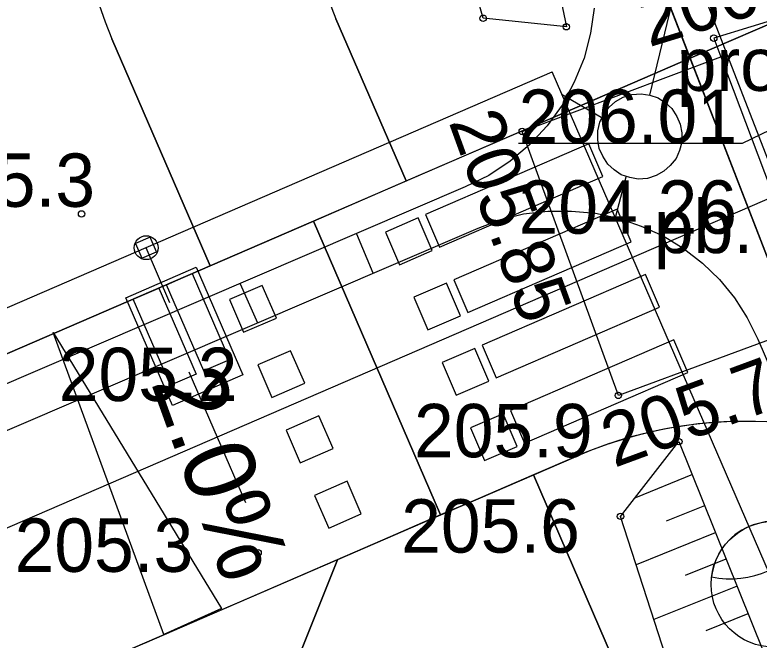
# Model space of a CAD drawing. Extents: x 6512606 to 6513006, y 6022524 to 6022728.
# Drawn here: x 6512842.35 to 6512852.81, y 6022585.95 to 6022594.74 of the extents above; entities that cross this region are included whole.
import ezdxf

# ---------------------------------------------------------------- set-up
doc = ezdxf.new("R2010")
doc.units = 0
for name, color, linetype in [('000 Inne (niezydentyfikowane)', 7, 'Continuous'), ('217-kontur klasyfikacyjny', 7, 'Continuous'), ('218-kontur użytku gruntowego', 7, 'Continuous'), ('219-działka ewidencyjna', 7, 'Continuous'), ('4', 7, 'Continuous'), ('Default', 7, 'Continuous'), ('E_OSW_KABLE', 7, 'Continuous'), ('E_OSW_LAMPA', 7, 'Continuous'), ('jezdnia', 7, 'Continuous'), ('kolor_chodnik', 7, 'Continuous'), ('kolor_kostka_bet', 7, 'Continuous'), ('kolor_sc_rowerowa', 7, 'Continuous'), ('krawężnik', 7, 'Continuous'), ('Level 60', 7, 'Continuous'), ('maxp_kan_deszczowa', 7, 'Continuous'), ('maxp_kraw_nawierzchni', 7, 'Continuous'), ('maxp_krawężnik', 7, 'Continuous'), ('maxp_obrzeże', 7, 'Continuous'), ('maxp_opornik', 7, 'Continuous'), ('maxp_os', 7, 'Continuous'), ('maxp_poziome', 7, 'Continuous'), ('maxp_przechyłki', 7, 'Continuous'), ('maxp_ramka_2', 7, 'Continuous'), ('obszar utwardzony', 7, 'Continuous'), ('obszar utwardzony-Atr17', 7, 'Continuous'), ('pikieta naturalna', 7, 'Continuous'), ('pikieta naturalna-Atr2', 7, 'Continuous'), ('pikieta sztuczna', 7, 'Continuous'), ('pikieta sztuczna-Atr2', 7, 'Continuous'), ('przewód kanalizacyjny - projektowany lub w budowie (linia) - ob. projektowany', 7, 'Continuous'), ('punkt o określonej wysokości (sieć kanalizacyjna)-Atr2', 7, 'Continuous'), ('punkt o określonej wysokości (sieć kanalizacyjna)-Atr3', 7, 'Continuous'), ('punkt wysokościowy naturalny-Atr2', 7, 'Continuous'), ('skarpa nieumocniona', 7, 'Continuous'), ('urządzenie techniczne projektowane lub w budowie (sieć kanalizacyjna) - powierzchnia - ob. projektowany', 7, 'Continuous'), ('urządzenie techniczne projektowane lub w budowie (sieć kanalizacyjna) - powierzchnia - ob. projektowany-Atr17', 7, 'Continuous')]:
    doc.layers.add(name, color=color, linetype=linetype)

# ---------------------------------------------------------------- blocks, each defined once
blk = doc.blocks.new('PW01')
at = {"layer": 'Default'}
blk.add_circle((0, 0), 0.45, dxfattribs=at)
blk = doc.blocks.new('RLX_5XB31K2B408A_46W_1')
at = {"layer": 'Default'}
for p, q in [((-53.8, 53.6), (-53.8, 218.5)), ((-53.8, 218.5), (54.2, 218.5)), ((54.2, 218.5), (54.2, 53.6)), ((-44.8, 59.5), (-44.8, 191.5)), ((-44.8, 191.5), (-5.8, 191.5)), ((-5.8, 191.5), (-5.8, 59.5)), ((6.2, 59.5), (6.2, 191.5)), ((6.2, 191.5), (45.2, 191.5)), ((45.2, 191.5), (45.2, 59.5)), ((-0.1, 84.6), (-0.1, 0.4)), ((54.2, 53.6), (-53.8, 53.6)), ((-5.8, 59.5), (-44.8, 59.5)), ((45.2, 59.5), (6.2, 59.5))]:
    blk.add_line(p, q, dxfattribs=at)
blk.add_lwpolyline([(11.2, -10.8), (11.2, 11.6), (-11.3, 11.6), (-11.3, -10.8)], close=True, dxfattribs=at)
blk.add_circle((-0.1, 0.4), 16.8, dxfattribs=at)

msp = doc.modelspace()

# ---------------------------------------------------------------- linework, layer by layer
at = {"layer": '000 Inne (niezydentyfikowane)'}
for points in [[(6512850.09, 6022594.6), (6512850.05, 6022594.59)], [(6512851.87, 6022588.28), (6512851.07, 6022587.95)], [(6512852.04, 6022587.84), (6512851.5, 6022587.62)], [(6512852.19, 6022587.46), (6512851.08, 6022587.01)], [(6512852.34, 6022587.09), (6512851.77, 6022586.86)], [(6512852.5, 6022586.71), (6512851.33, 6022586.24)], [(6512852.65, 6022586.32), (6512852.06, 6022586.08)]]:
    msp.add_lwpolyline(points, dxfattribs=at)
at = {"layer": '217-kontur klasyfikacyjny'}
msp.add_lwpolyline([(6512855.78, 6022583.95), (6512848.55, 6022602.62)], dxfattribs=at)
at = {"layer": '218-kontur użytku gruntowego'}
for points in [[(6512848.55, 6022602.62), (6512855.78, 6022583.95)], [(6512855.78, 6022583.95), (6512848.55, 6022602.62)]]:
    msp.add_lwpolyline(points, dxfattribs=at)
at = {"layer": '219-działka ewidencyjna'}
msp.add_lwpolyline([(6512855.78, 6022583.95), (6512848.55, 6022602.62)], dxfattribs=at)
at = {"layer": '4'}
msp.add_lwpolyline([(6512855.78, 6022583.95), (6512848.55, 6022602.62)], dxfattribs=at)
at = {"layer": 'E_OSW_KABLE'}
msp.add_line((6512835.613, 6022587.752), (6512849.902, 6022593.935), dxfattribs=at)
msp.add_lwpolyline([(6512855.264, 6022584.708), (6512853.876, 6022584.751), (6512849.902, 6022593.935)], dxfattribs=at)
at = {"layer": 'E_OSW_LAMPA'}
msp.add_circle((6512853.018, 6022586.735), 0.885, dxfattribs=at)
for centre, radius, start, end in [((6512853.018, 6022586.735), 0.885, 53.2802, 173.2802), ((6512852.398, 6022588.175), 1.362, 259.0508, 327.5095)]:
    msp.add_arc(centre, radius, start, end, dxfattribs=at)
at = {"layer": 'jezdnia'}
msp.add_lwpolyline([(6512857.23, 6022588.82), (6512855.05, 6022597.75), (6512854.94, 6022596.77), (6512854.71, 6022596.06), (6512854.24, 6022595.41), (6512853.71, 6022594.99), (6512853.21, 6022594.73), (6512852.17, 6022594.41), (6512852.27, 6022594.15), (6512853.67, 6022590.44), (6512853.87, 6022590.02), (6512854.31, 6022590.11), (6512855.01, 6022590.11), (6512855.7, 6022590.01), (6512856.23, 6022589.8), (6512856.78, 6022589.31)], close=True, dxfattribs=at)
at = {"layer": 'kolor_chodnik'}
for p, q in [((6512851.838, 6022594.128), (6512853.234, 6022594.732)), ((6512846.864, 6022594.682), (6512847.85, 6022592.403)), ((6512850.218, 6022593.427), (6512851.838, 6022594.128)), ((6512847.85, 6022592.403), (6512850.218, 6022593.427)), ((6512850.236, 6022588.532), (6512849.637, 6022588.273)), ((6512849.637, 6022588.273), (6512851.225, 6022584.602))]:
    msp.add_line(p, q, dxfattribs=at)
for centre, radius, start, end in [((6512849.617, 6022595.874), 3, 113.9, 203.397), ((6512852.619, 6022583.025), 6, 48.3268, 113.397)]:
    msp.add_arc(centre, radius, start, end, dxfattribs=at)
at = {"layer": 'kolor_kostka_bet'}
for p, q in [((6512853.234, 6022594.732), (6512851.838, 6022594.128)), ((6512845.097, 6022591.211), (6512843.717, 6022594.401)), ((6512851.838, 6022594.128), (6512850.218, 6022593.427)), ((6512850.218, 6022593.427), (6512846.547, 6022591.839)), ((6512846.547, 6022591.839), (6512835.634, 6022587.117)), ((6512846.547, 6022591.839), (6512848.334, 6022587.709)), ((6512848.334, 6022587.709), (6512846.547, 6022591.839)), ((6512846.547, 6022591.839), (6512848.334, 6022587.709)), ((6512835.634, 6022587.117), (6512845.097, 6022591.211)), ((6512848.859, 6022587.936), (6512850.236, 6022588.532)), ((6512848.334, 6022587.709), (6512848.859, 6022587.936)), ((6512844.176, 6022585.91), (6512848.334, 6022587.709)), ((6512846.363, 6022585.766), (6512846.884, 6022587.081))]:
    msp.add_line(p, q, dxfattribs=at)
msp.add_lwpolyline([(6512846.884, 6022587.081), (6512844.176, 6022585.91), (6512843.862, 6022585.774)], dxfattribs=at)
for centre, radius, start, end in [((6512848.305, 6022596.386), 5, 113.9, 203.397), ((6512852.619, 6022583.025), 6, 14.633, 113.397)]:
    msp.add_arc(centre, radius, start, end, dxfattribs=at)
at = {"layer": 'kolor_sc_rowerowa'}
for p, q in [((6512847.85, 6022592.403), (6512846.864, 6022594.682)), ((6512843.717, 6022594.401), (6512845.097, 6022591.211)), ((6512846.547, 6022591.839), (6512847.85, 6022592.403)), ((6512845.097, 6022591.211), (6512846.547, 6022591.839)), ((6512849.637, 6022588.273), (6512848.859, 6022587.936)), ((6512851.225, 6022584.602), (6512849.637, 6022588.273)), ((6512848.859, 6022587.936), (6512848.334, 6022587.709)), ((6512848.334, 6022587.709), (6512846.884, 6022587.081)), ((6512846.884, 6022587.081), (6512846.363, 6022585.766))]:
    msp.add_line(p, q, dxfattribs=at)
for centre, radius in [((6512848.305, 6022596.386), 5), ((6512849.617, 6022595.874), 3)]:
    msp.add_arc(centre, radius, 113.9, 203.397, dxfattribs=at)
at = {"layer": 'krawężnik'}
msp.add_lwpolyline([(6512857.23, 6022588.82), (6512855.05, 6022597.75), (6512854.94, 6022596.77), (6512854.71, 6022596.06), (6512854.24, 6022595.41), (6512853.71, 6022594.99), (6512853.21, 6022594.73), (6512852.17, 6022594.41), (6512852.27, 6022594.15), (6512853.67, 6022590.44), (6512853.87, 6022590.02), (6512854.31, 6022590.11), (6512855.01, 6022590.11), (6512855.7, 6022590.01), (6512856.23, 6022589.8), (6512856.78, 6022589.31)], close=True, dxfattribs=at)
at = {"layer": 'Level 60'}
msp.add_lwpolyline([(6512844.799, 6022589.721), (6512845.593, 6022587.885)], dxfattribs=at)
at = {"layer": 'maxp_kan_deszczowa'}
msp.add_lwpolyline([(6512855.131, 6022585.797), (6512853.495, 6022589.851), (6512851.482, 6022595.049), (6512848.64, 6022602.387)], dxfattribs=at)
at = {"layer": 'maxp_kraw_nawierzchni'}
for p, q in [((6512847.85, 6022592.403), (6512846.864, 6022594.682)), ((6512848.017, 6022591.885), (6512847.558, 6022591.686)), ((6512848.215, 6022591.426), (6512848.017, 6022591.885)), ((6512847.558, 6022591.686), (6512847.757, 6022591.227)), ((6512847.757, 6022591.227), (6512848.215, 6022591.426)), ((6512845.827, 6022590.936), (6512845.369, 6022590.737)), ((6512846.026, 6022590.477), (6512845.827, 6022590.936)), ((6512848.414, 6022590.967), (6512847.955, 6022590.768)), ((6512848.613, 6022590.508), (6512848.414, 6022590.967)), ((6512845.369, 6022590.737), (6512845.567, 6022590.278)), ((6512847.955, 6022590.768), (6512848.154, 6022590.309)), ((6512845.567, 6022590.278), (6512846.026, 6022590.477)), ((6512848.154, 6022590.309), (6512848.613, 6022590.508)), ((6512851.608, 6022590.172), (6512849.314, 6022589.177)), ((6512851.807, 6022589.713), (6512851.608, 6022590.172)), ((6512846.225, 6022590.018), (6512845.766, 6022589.819)), ((6512846.424, 6022589.56), (6512846.225, 6022590.018)), ((6512848.812, 6022590.049), (6512848.353, 6022589.851)), ((6512849.011, 6022589.591), (6512848.812, 6022590.049)), ((6512845.766, 6022589.819), (6512845.965, 6022589.361)), ((6512848.353, 6022589.851), (6512848.552, 6022589.392)), ((6512849.513, 6022588.719), (6512851.807, 6022589.713)), ((6512848.552, 6022589.392), (6512849.011, 6022589.591)), ((6512845.965, 6022589.361), (6512846.424, 6022589.56)), ((6512849.314, 6022589.177), (6512849.513, 6022588.719)), ((6512846.623, 6022589.101), (6512846.164, 6022588.902)), ((6512846.822, 6022588.642), (6512846.623, 6022589.101)), ((6512846.164, 6022588.902), (6512846.363, 6022588.443)), ((6512846.363, 6022588.443), (6512846.822, 6022588.642)), ((6512851.225, 6022584.602), (6512849.637, 6022588.273)), ((6512847.021, 6022588.183), (6512846.562, 6022587.984)), ((6512847.219, 6022587.724), (6512847.021, 6022588.183)), ((6512846.562, 6022587.984), (6512846.761, 6022587.526)), ((6512846.761, 6022587.526), (6512847.219, 6022587.724))]:
    msp.add_line(p, q, dxfattribs=at)
msp.add_arc((6512849.617, 6022595.874), 3, 113.9, 203.397, dxfattribs=at)
at = {"layer": 'maxp_krawężnik'}
for p, q in [((6512853.234, 6022594.732), (6512850.218, 6022593.427)), ((6512845.097, 6022591.211), (6512835.634, 6022587.117)), ((6512846.884, 6022587.081), (6512841.909, 6022584.929))]:
    msp.add_line(p, q, dxfattribs=at)
msp.add_arc((6512852.619, 6022583.025), 6, 14.633, 94.6616, dxfattribs=at)
at = {"layer": 'maxp_obrzeże'}
for p, q in [((6512845.097, 6022591.211), (6512843.717, 6022594.401)), ((6512846.363, 6022585.766), (6512846.884, 6022587.081))]:
    msp.add_line(p, q, dxfattribs=at)
msp.add_arc((6512848.305, 6022596.386), 5, 113.9, 203.397, dxfattribs=at)
at = {"layer": 'maxp_opornik'}
for p, q in [((6512850.218, 6022593.427), (6512845.097, 6022591.211)), ((6512850.236, 6022588.532), (6512848.859, 6022587.936)), ((6512848.859, 6022587.936), (6512846.884, 6022587.081))]:
    msp.add_line(p, q, dxfattribs=at)
msp.add_arc((6512852.619, 6022583.025), 6, 94.6616, 113.397, dxfattribs=at)
at = {"layer": 'maxp_os'}
msp.add_line((6512859.416, 6022594.955), (6512836.66, 6022585.109), dxfattribs=at)
at = {"layer": 'maxp_poziome'}
for p, q in [((6512850.415, 6022592.924), (6512848.121, 6022591.93)), ((6512850.614, 6022592.465), (6512850.415, 6022592.924)), ((6512848.32, 6022591.471), (6512850.614, 6022592.465)), ((6512850.813, 6022592.007), (6512848.519, 6022591.012)), ((6512851.012, 6022591.548), (6512850.813, 6022592.007)), ((6512848.017, 6022591.885), (6512847.558, 6022591.686)), ((6512848.215, 6022591.426), (6512848.017, 6022591.885)), ((6512848.121, 6022591.93), (6512848.32, 6022591.471)), ((6512847.558, 6022591.686), (6512847.757, 6022591.227)), ((6512848.718, 6022590.554), (6512851.012, 6022591.548)), ((6512847.757, 6022591.227), (6512848.215, 6022591.426)), ((6512851.21, 6022591.089), (6512848.917, 6022590.095)), ((6512851.409, 6022590.63), (6512851.21, 6022591.089)), ((6512845.827, 6022590.936), (6512845.369, 6022590.737)), ((6512846.026, 6022590.477), (6512845.827, 6022590.936)), ((6512848.414, 6022590.967), (6512847.955, 6022590.768)), ((6512848.613, 6022590.508), (6512848.414, 6022590.967)), ((6512848.519, 6022591.012), (6512848.718, 6022590.554)), ((6512845.369, 6022590.737), (6512845.567, 6022590.278)), ((6512847.955, 6022590.768), (6512848.154, 6022590.309)), ((6512849.115, 6022589.636), (6512851.409, 6022590.63)), ((6512845.567, 6022590.278), (6512846.026, 6022590.477)), ((6512848.154, 6022590.309), (6512848.613, 6022590.508)), ((6512848.917, 6022590.095), (6512849.115, 6022589.636)), ((6512851.608, 6022590.172), (6512849.314, 6022589.177)), ((6512851.807, 6022589.713), (6512851.608, 6022590.172)), ((6512846.225, 6022590.018), (6512845.766, 6022589.819)), ((6512846.424, 6022589.56), (6512846.225, 6022590.018)), ((6512848.812, 6022590.049), (6512848.353, 6022589.851)), ((6512849.011, 6022589.591), (6512848.812, 6022590.049)), ((6512845.766, 6022589.819), (6512845.965, 6022589.361)), ((6512848.353, 6022589.851), (6512848.552, 6022589.392)), ((6512849.513, 6022588.719), (6512851.807, 6022589.713)), ((6512848.552, 6022589.392), (6512849.011, 6022589.591)), ((6512845.965, 6022589.361), (6512846.424, 6022589.56)), ((6512849.314, 6022589.177), (6512849.513, 6022588.719)), ((6512846.623, 6022589.101), (6512846.164, 6022588.902)), ((6512846.822, 6022588.642), (6512846.623, 6022589.101)), ((6512849.21, 6022589.132), (6512848.751, 6022588.933)), ((6512849.408, 6022588.673), (6512849.21, 6022589.132)), ((6512846.164, 6022588.902), (6512846.363, 6022588.443)), ((6512848.751, 6022588.933), (6512848.95, 6022588.474)), ((6512846.363, 6022588.443), (6512846.822, 6022588.642)), ((6512848.95, 6022588.474), (6512849.408, 6022588.673)), ((6512847.021, 6022588.183), (6512846.562, 6022587.984)), ((6512847.219, 6022587.724), (6512847.021, 6022588.183)), ((6512846.562, 6022587.984), (6512846.761, 6022587.526)), ((6512846.761, 6022587.526), (6512847.219, 6022587.724))]:
    msp.add_line(p, q, dxfattribs=at)
at = {"layer": 'maxp_przechyłki'}
msp.add_lwpolyline([(6512842.893, 6022590.276), (6512845.258, 6022586.396), (6512844.444, 6022586.031)], close=True, dxfattribs=at)
at = {"layer": 'maxp_ramka_2'}
msp.add_line((6512848.827, 6022603.29), (6512856.423, 6022583.675), dxfattribs=at)
at = {"layer": 'obszar utwardzony'}
msp.add_lwpolyline([(6512853.67, 6022590.44), (6512850.83, 6022589.39), (6512849.48, 6022593.1), (6512852.27, 6022594.15)], close=True, dxfattribs=at)
at = {"layer": 'przewód kanalizacyjny - projektowany lub w budowie (linia) - ob. projektowany'}
for points in [[(6512851.27, 6022593.61), (6512852.18, 6022597.37), (6512857.2, 6022600.23)], [(6512850.04, 6022593.62), (6512850.59, 6022593.3)], [(6512850.79, 6022591.89), (6512850.94, 6022592.46)]]:
    msp.add_lwpolyline(points, dxfattribs=at)
at = {"layer": 'punkt o określonej wysokości (sieć kanalizacyjna)-Atr2'}
msp.add_lwpolyline([(6512856.13, 6022594.65), (6512852.57, 6022592.93), (6512849.429, 6022592.93)], dxfattribs=at)
at = {"layer": 'skarpa nieumocniona'}
for points in [[(6512847.69, 6022599.05), (6512848.99, 6022599.84), (6512850.1, 6022594.57), (6512848.93, 6022594.69)], [(6512847.69, 6022599.05), (6512848.99, 6022599.84), (6512850.1, 6022594.57), (6512848.93, 6022594.69)], [(6512851.68, 6022588.74), (6512853.54, 6022584.12), (6512852.35, 6022583.09), (6512850.86, 6022587.69)], [(6512851.68, 6022588.74), (6512853.54, 6022584.12), (6512852.35, 6022583.09), (6512850.86, 6022587.69)]]:
    msp.add_lwpolyline(points, close=True, dxfattribs=at)
at = {"layer": 'urządzenie techniczne projektowane lub w budowie (sieć kanalizacyjna) - powierzchnia - ob. projektowany'}
for points in [[(6512850.49, 6022594.83), (6512850.44, 6022594.48), (6512850.35, 6022594.13), (6512850.21, 6022593.79), (6512850.04, 6022593.47), (6512849.83, 6022593.18), (6512849.58, 6022592.91), (6512849.31, 6022592.68), (6512849.01, 6022592.48), (6512848.68, 6022592.32), (6512816.84, 6022578.64)], [(6512817.02, 6022578.07), (6512848.86, 6022591.74), (6512849.18, 6022591.86), (6512849.5, 6022591.94), (6512849.84, 6022591.98), (6512850.17, 6022591.98), (6512850.51, 6022591.95), (6512850.83, 6022591.88), (6512851.15, 6022591.77), (6512851.46, 6022591.63), (6512851.74, 6022591.46), (6512852.01, 6022591.25), (6512852.25, 6022591.02), (6512852.46, 6022590.76), (6512852.64, 6022590.48), (6512852.79, 6022590.18), (6512853.66, 6022588.16), (6512853.77, 6022587.85), (6512853.85, 6022587.52), (6512853.89, 6022587.19), (6512853.9, 6022586.85), (6512853.86, 6022586.52), (6512853.79, 6022586.19), (6512853.69, 6022585.87)], [(6512847.15, 6022591.66), (6512847.38, 6022591.11)], [(6512845.52, 6022590.96), (6512845.76, 6022590.41)]]:
    msp.add_lwpolyline(points, dxfattribs=at)
msp.add_lwpolyline([(6512851.15, 6022593.63), (6512851.27, 6022593.61), (6512851.39, 6022593.57), (6512851.49, 6022593.5), (6512851.58, 6022593.42), (6512851.65, 6022593.31), (6512851.7, 6022593.2), (6512851.72, 6022593.08), (6512851.72, 6022592.95), (6512851.69, 6022592.83), (6512851.64, 6022592.72), (6512851.56, 6022592.62), (6512851.47, 6022592.54), (6512851.36, 6022592.48), (6512851.24, 6022592.44), (6512851.11, 6022592.43), (6512850.99, 6022592.45), (6512850.87, 6022592.49), (6512850.77, 6022592.56), (6512850.68, 6022592.64), (6512850.61, 6022592.75), (6512850.56, 6022592.86), (6512850.54, 6022592.98), (6512850.54, 6022593.11), (6512850.57, 6022593.23), (6512850.62, 6022593.34), (6512850.7, 6022593.44), (6512850.79, 6022593.52), (6512850.9, 6022593.58), (6512851.02, 6022593.62)], close=True, dxfattribs=at)

# ---------------------------------------------------------------- block references
at = {"layer": 'E_OSW_LAMPA', "xscale": 0.010000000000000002, "yscale": 0.010000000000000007, "rotation": -156.60297735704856}
msp.add_blockref('RLX_5XB31K2B408A_46W_1', (6512844.195, 6022591.469), dxfattribs=at)
at = {"layer": 'pikieta naturalna', "xscale": 0.1, "yscale": 0.10000000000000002}
for p in [(6512848.93, 6022594.69), (6512850.1, 6022594.57), (6512843.29, 6022591.94), (6512851.68, 6022588.74), (6512850.86, 6022587.69), (6512845.77, 6022587.18)]:
    msp.add_blockref('PW01', p, dxfattribs=at)
at = {"layer": 'pikieta sztuczna', "xscale": 0.1, "yscale": 0.10000000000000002}
for p in [(6512852.17, 6022594.41), (6512849.48, 6022593.1), (6512850.83, 6022589.39)]:
    msp.add_blockref('PW01', p, dxfattribs=at)

# ---------------------------------------------------------------- texts
at = {"layer": 'maxp_przechyłki'}
msp.add_text('2.0%', height=1, rotation=289.8994, dxfattribs=at).set_placement((6512844.26, 6022589.571))
at = {"layer": 'obszar utwardzony-Atr17'}
msp.add_text('pb.', height=0.75, dxfattribs=at).set_placement((6512851.33, 6022591.39))
at = {"layer": 'pikieta naturalna-Atr2'}
for s, p in [('205.9', (6512847.96, 6022588.52)), ('205.6', (6512847.78, 6022587.18)), ('205.3', (6512842.35, 6022586.91))]:
    msp.add_text(s, height=0.75, dxfattribs=at).set_placement(p)
at = {"layer": 'pikieta sztuczna-Atr2'}
for s, rotation, p in [('206.14', 17.103, (6512851.261, 6022594.281)), ('205.85', 289.996, (6512848.442, 6022593.236)), ('205.79', 20.29, (6512850.772, 6022588.369))]:
    msp.add_text(s, height=0.75, rotation=rotation, dxfattribs=at).set_placement(p)
at = {"layer": 'punkt o określonej wysokości (sieć kanalizacyjna)-Atr2'}
msp.add_text('206.01', height=0.75, dxfattribs=at).set_placement((6512849.429, 6022592.938))
at = {"layer": 'punkt o określonej wysokości (sieć kanalizacyjna)-Atr3'}
msp.add_text('204.26', height=0.75, dxfattribs=at).set_placement((6512849.429, 6022591.662))
at = {"layer": 'punkt wysokościowy naturalny-Atr2'}
for s, p in [('205.3', (6512840.97, 6022592.04)), ('205.2', (6512842.97, 6022589.31))]:
    msp.add_text(s, height=0.75, dxfattribs=at).set_placement(p)
at = {"layer": 'urządzenie techniczne projektowane lub w budowie (sieć kanalizacyjna) - powierzchnia - ob. projektowany-Atr17'}
msp.add_text('proj. k', height=0.75, dxfattribs=at).set_placement((6512851.65, 6022593.67))

doc.saveas('drawing.dxf')
